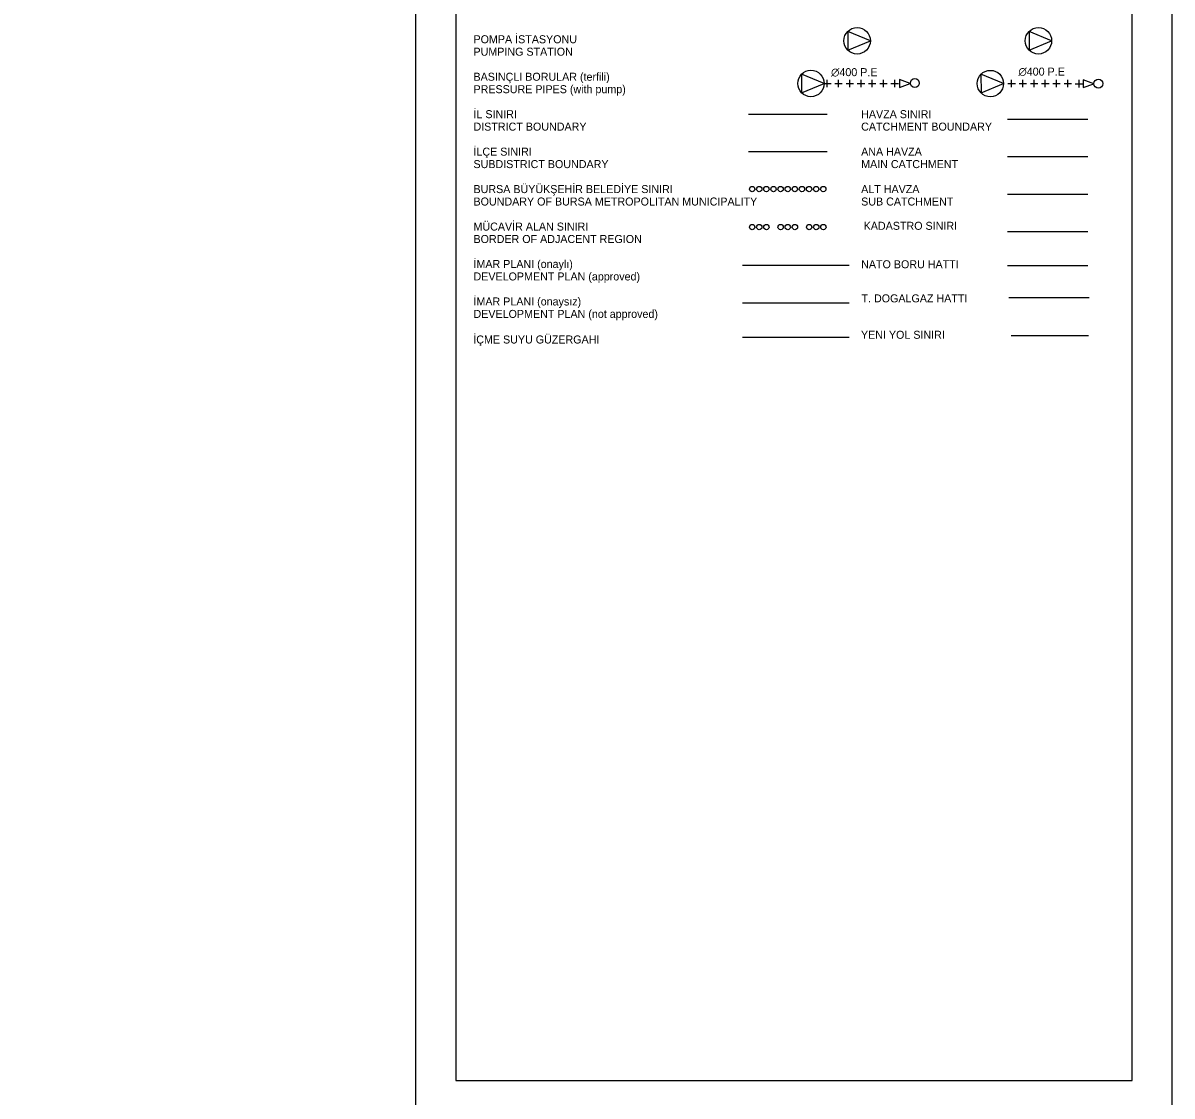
# Model space of a CAD drawing. Extents: x -10 to 1145, y -10 to 821.
# Drawn here: x 856.2 to 1145, y 283.1 to 552.8 of the extents above; entities that cross this region are included whole.
import ezdxf

# ---------------------------------------------------------------- set-up
doc = ezdxf.new("R2010")
doc.units = 0
for name, color, linetype in [('Level 1', 7, 'Continuous'), ('Level 25', 7, 'Continuous'), ('Level 30', 7, 'Continuous'), ('Level 36', 7, 'Continuous'), ('Level 37', 7, 'Continuous'), ('Level 38', 7, 'Continuous'), ('Level 39', 7, 'Continuous'), ('Level 47', 7, 'Continuous'), ('Level 50', 7, 'Continuous'), ('Level 51', 7, 'Continuous'), ('Level 52', 7, 'Continuous'), ('Level 57', 7, 'Continuous'), ('Level 62', 7, 'Continuous')]:
    doc.layers.add(name, color=color, linetype=linetype)

msp = doc.modelspace()

# ---------------------------------------------------------------- linework, layer by layer
at = {"layer": 'Level 1'}
for p, q in [((1057.43, 537.63), (1059.31, 537.63)), ((1058.37, 536.69), (1058.37, 538.58)), ((1060.25, 537.63), (1062.14, 537.63)), ((1061.2, 536.69), (1061.2, 538.58)), ((1063.08, 537.63), (1064.96, 537.63)), ((1064.02, 536.69), (1064.02, 538.58)), ((1065.9, 537.63), (1067.79, 537.63)), ((1066.85, 536.69), (1066.85, 538.58)), ((1068.73, 537.63), (1070.61, 537.63)), ((1069.67, 536.69), (1069.67, 538.58)), ((1071.55, 537.63), (1073.44, 537.63)), ((1072.49, 536.69), (1072.49, 538.58)), ((1074.38, 537.63), (1076.26, 537.63)), ((1075.32, 536.69), (1075.32, 538.58)), ((1103.75, 537.62), (1105.63, 537.62)), ((1104.69, 536.68), (1104.69, 538.56)), ((1106.57, 537.62), (1108.45, 537.62)), ((1107.51, 536.68), (1107.51, 538.56)), ((1109.4, 537.62), (1111.28, 537.62)), ((1110.34, 536.68), (1110.34, 538.56)), ((1112.22, 537.62), (1114.1, 537.62)), ((1113.16, 536.68), (1113.16, 538.56)), ((1115.04, 537.62), (1116.93, 537.62)), ((1115.99, 536.68), (1115.99, 538.56)), ((1117.87, 537.62), (1119.75, 537.62)), ((1118.81, 536.68), (1118.81, 538.56)), ((1120.69, 537.59), (1122.58, 537.59)), ((1121.63, 536.65), (1121.63, 538.53)), ((1103.63, 500.44), (1123.83, 500.44)), ((1103.63, 491.89), (1123.83, 491.89)), ((1103.98, 483.86), (1124.19, 483.86))]:
    msp.add_line(p, q, dxfattribs=at)
for points in [[(1051.92, 539.98), (1051.92, 535.28), (1057.59, 537.64)], [(1079.22, 537.63), (1076.52, 538.6), (1076.52, 536.67)], [(1096.99, 539.96), (1097.01, 535.26), (1102.67, 537.64)], [(1125.39, 537.58), (1122.69, 538.55), (1122.69, 536.62)]]:
    msp.add_lwpolyline(points, close=True, dxfattribs=at)
for centre, radius in [((1054.27, 537.64), 3.32), ((1099.35, 537.62), 3.32), ((1080.37, 537.73), 1.13), ((1126.51, 537.6), 1.13)]:
    msp.add_circle(centre, radius, dxfattribs=at)
at = {"layer": 'Level 25'}
for points in [[(1063.52, 550.72), (1063.52, 546.02), (1069.2, 548.37)], [(1109.06, 550.71), (1109.08, 546.01), (1114.74, 548.39)]]:
    msp.add_lwpolyline(points, close=True, dxfattribs=at)
for centre in [(1065.87, 548.37), (1111.42, 548.37)]:
    msp.add_circle(centre, 3.32, dxfattribs=at)
at = {"layer": 'Level 30'}
for p, q in [((1103.63, 528.68), (1123.83, 528.68)), ((1103.63, 519.27), (1123.83, 519.27)), ((1103.63, 509.85), (1123.83, 509.85))]:
    msp.add_line(p, q, dxfattribs=at)
at = {"layer": 'Level 36'}
msp.add_line((1038.59, 529.92), (1058.33, 529.92), dxfattribs=at)
at = {"layer": 'Level 37'}
msp.add_line((1038.59, 520.51), (1058.33, 520.51), dxfattribs=at)
at = {"layer": 'Level 38'}
for centre in [(1039.49, 511.09), (1039.49, 511.09), (1041.27, 511.09), (1041.27, 511.09), (1043.06, 511.09), (1043.06, 511.09), (1044.85, 511.09), (1044.85, 511.09), (1046.64, 511.09), (1046.64, 511.09), (1048.43, 511.09), (1048.43, 511.09), (1050.22, 511.09), (1050.22, 511.09), (1052.01, 511.09), (1052.01, 511.09), (1053.8, 511.09), (1053.8, 511.09), (1055.58, 511.09), (1055.58, 511.09), (1057.37, 511.09), (1057.37, 511.09)]:
    msp.add_circle(centre, 0.671, dxfattribs=at)
at = {"layer": 'Level 39'}
for centre in [(1039.5, 501.55), (1039.5, 501.55), (1041.28, 501.55), (1041.28, 501.55), (1043.07, 501.55), (1043.07, 501.55), (1046.65, 501.55), (1046.65, 501.55), (1048.44, 501.55), (1048.44, 501.55), (1050.23, 501.55), (1050.23, 501.55), (1053.81, 501.55), (1053.81, 501.55), (1055.6, 501.55), (1055.6, 501.55), (1057.38, 501.55), (1057.38, 501.55)]:
    msp.add_circle(centre, 0.671, dxfattribs=at)
at = {"layer": 'Level 47'}
msp.add_line((1037.04, 491.94), (1063.87, 491.94), dxfattribs=at)
at = {"layer": 'Level 50'}
msp.add_lwpolyline([(0, 0), (955, 0), (955, 811), (0, 811)], close=True, dxfattribs=at)
at = {"layer": 'Level 51'}
msp.add_lwpolyline([(-10, -10), (1145, -10), (1145, 821), (-10, 821)], close=True, dxfattribs=at)
at = {"layer": 'Level 52'}
msp.add_lwpolyline([(965, 287), (1135, 287), (1135, 811), (965, 811)], close=True, dxfattribs=at)
at = {"layer": 'Level 57'}
msp.add_line((1037.04, 482.53), (1063.87, 482.53), dxfattribs=at)
at = {"layer": 'Level 62'}
for p, q in [((1037.04, 473.88), (1063.87, 473.88)), ((1104.55, 474.32), (1124.05, 474.32))]:
    msp.add_line(p, q, dxfattribs=at)

# ---------------------------------------------------------------- texts
at = {"layer": 'Level 1'}
for s, height, rotation, p in [('POMPA İSTASYONU', 2.0119, 360, (969.46, 547.75)), ('PUMPING STATION', 2.0119, 360, (969.46, 544.62)), ('BASINÇLI BORULAR (terfili)', 2.0119, 360, (969.46, 538.33)), ('∅400 P.E', 2.012, 359.987, (1059.33, 539.48)), ('∅400 P.E', 2.012, 359.987, (1106.41, 539.62)), ('PRESSURE PIPES (with pump)', 2.0119, 360, (969.46, 535.2)), ('İL SINIRI', 2.012, 360, (969.46, 528.92)), ('HAVZA SINIRI', 2.0119, 360, (1066.88, 528.92)), ('DISTRICT BOUNDARY', 2.0119, 360, (969.46, 525.79)), ('CATCHMENT BOUNDARY', 2.0119, 360, (1066.88, 525.79)), ('İLÇE SINIRI', 2.0119, 360, (969.46, 519.5)), ('ANA HAVZA', 2.012, 360, (1066.88, 519.5)), ('SUBDISTRICT BOUNDARY', 2.0119, 360, (969.46, 516.37)), ('MAIN CATCHMENT', 2.0119, 360, (1066.88, 516.37)), ('BURSA BÜYÜKŞEHİR BELEDİYE SINIRI', 2.0119, 360, (969.46, 510.09)), ('ALT HAVZA', 2.012, 360, (1066.88, 510.09)), ('BOUNDARY OF BURSA METROPOLITAN MUNICIPALITY', 2.0119, 360, (969.46, 506.96)), ('SUB CATCHMENT', 2.0119, 360, (1066.88, 506.96)), ('MÜCAVİR ALAN SINIRI', 2.0119, 360, (969.46, 500.67)), ('BORDER OF ADJACENT REGION', 2.0119, 360, (969.46, 497.54)), ('İMAR PLANI (onaylı)', 2.0119, 360, (969.46, 491.26)), ('NATO BORU HATTI', 2.0119, 360, (1066.88, 491.19)), ('DEVELOPMENT PLAN (approved)', 2.0119, 360, (969.46, 488.13)), ('İMAR PLANI (onaysız)', 2.0119, 360, (969.46, 481.84)), ('T. DOGALGAZ HATTI', 2.0119, 360, (1066.97, 482.62)), ('DEVELOPMENT PLAN (not approved)', 2.0119, 360, (969.46, 478.71))]:
    msp.add_text(s, height=height, rotation=rotation, dxfattribs=at).set_placement(p)
at = {"layer": 'Level 25'}
msp.add_text('KADASTRO SINIRI', height=2.0119, dxfattribs=at).set_placement((1067.51, 500.86))
at = {"layer": 'Level 62'}
for s, p in [('İÇME SUYU GÜZERGAHI', (969.41, 472.28)), ('YENI YOL SINIRI', (1066.83, 473.47))]:
    msp.add_text(s, height=2.0119, rotation=360, dxfattribs=at).set_placement(p)

doc.saveas('drawing.dxf')
